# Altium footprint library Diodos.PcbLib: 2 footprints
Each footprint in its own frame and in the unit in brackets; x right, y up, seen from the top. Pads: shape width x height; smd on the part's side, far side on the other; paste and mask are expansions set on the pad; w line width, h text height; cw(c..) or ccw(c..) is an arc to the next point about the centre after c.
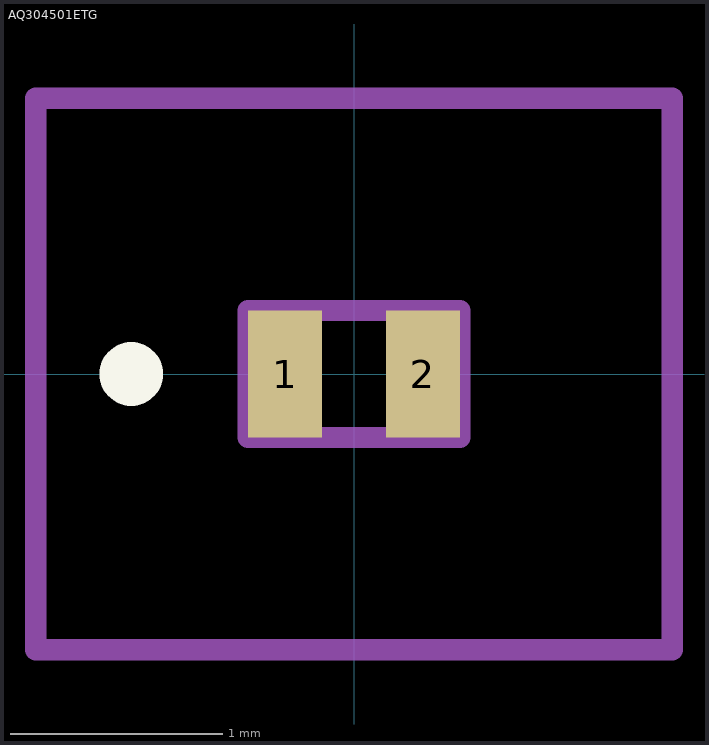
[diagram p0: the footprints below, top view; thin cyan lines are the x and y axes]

## AQ304501ETG [mm]
pads (2):
  rect 0.35x0.6 smd: 1(-0.325,0) 2(0.325,0)
Top Overlay:
  lines w0.2: -1.1,0 cw(c-1.05,0) -1,0 ; -1.1,0 ccw(c-1.05,0) -1,0 ; -1.1,0 cw(c-1.05,0) -1,0
Mechanical 13:
  lines w0.1: -0.5,-0.3 -0.5,0.3 0.5,0.3 0.5,-0.3 -0.5,-0.3
Mechanical 15:
  lines w0.1: -1.5,-1.3 -1.5,1.3 1.5,1.3 1.5,-1.3 -1.5,-1.3
3D body "AQ3045-01ETG.stp": height 0.43, standoff 0, extent -0.535,-0.34 0.535,0.335

## PCBComponent_1 [mm]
